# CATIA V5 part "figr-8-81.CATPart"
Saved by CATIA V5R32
Part number: Part1
Bounding box of the stored display mesh (mm): x -52.625 to 52.625, y -77.625 to 77.625, z 0 to 30
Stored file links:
  D:\PROJECTS\Project 2022\CATIA V5 6R 2022\Resources\Part Files\c08_catia_v5_6r2022_prt\figr-8-81.CATPart
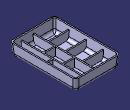
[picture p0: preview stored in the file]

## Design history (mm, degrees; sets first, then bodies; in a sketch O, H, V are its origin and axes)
Set1
  Plane1: type Offset, RefPlane xy-plane, Offset 30
  Plane2: type Offset, RefPlane face of Pad1, Offset -8, reversed
Body1 (main body)
  Sketch1 on xy-plane, origin (0, 0, 0), H (1, 0, 0), V (0, 1, 0)
    line L1 (-50, 75) -> (50, 75)
    line L2 (50, 75) -> (50, -75)
    line L3 (50, -75) -> (-50, -75)
    line L4 (-50, -75) -> (-50, 75)
    axis line L5 (50, -75) -> (-50, 75)
    length L3 = 100
    length L2 = 150
    horizontal: L1 H, L3 H
    vertical: L2 V, L4 V
    midpoint: O L5
  Pad1: profile Sketch1, direction (0, 0, 1), length 0, opposite side up to Plane1
  Draft1: Angle -5, Neutral face of Pad1, PullDir face of Pad1, SupportToDraft (face of Pad1; face of Pad1; face of Pad1; face of Pad1)
  Fillet1: radius 7, on edge [face of Pad1 | face of Pad1] (x4)
  Fillet2: radius 10, on edge [face of Pad1 | face of Pad1] (x4)
  Shell1: ExtOffset 0, Face face of Pad1, IntOffset 3
  Sketch2 on Plane2, origin (0, 0, 22), H (1, 0, 0), V (0, -1, 0)
    line L1 (28.1747, 54.0191) -> (28.1747, -59.2866)
    line L2 (0, 54.0191) -> (0, -59.2866)
    point P3 (0, 54.0191)
    line L3 (-9.5939, 0) -> (-33.0562, 0)
    point P5 (-9.5939, 0)
    line L4 (-9.5939, -40.4023) -> (-33.0562, -40.4023)
    point P7 (-9.5939, -40.4023)
    point P8 (-33.0562, -40.4023)
    point P9 (-33.0562, 40.4023)
    point P10 (-9.5939, 40.4023)
    line L5 (-9.5939, 40.4023) -> (-33.0562, 40.4023)
    line L6 (28.1747, 22.6983) -> (0, 22.6983)
    point P11 (28.1747, 22.6983)
    point P12 (0, 22.6983)
    point P13 (0, -22.6983)
    point P14 (28.1747, -22.6983)
    line L7 (28.1747, -22.6983) -> (0, -22.6983)
    line L8 (28.1747, 0) -> (41.8849, 0)
    point P15 (28.1747, 0)
    vertical: L1 V, L2 V
    coincidence: P3 V, P5 H, P11 L1, P12 L2, P15 L1, P15 H
    horizontal: L3 H, L4 H, L6 H, L8 H
    symmetry: P8 P9 L3, P7 P10 L3, L4 L5 L3, P12 P13 H, P11 P14 H, L6 L7 H
  Stiffener1: ExtendedProfile Sketch2, ThicknessTop 1, ThicknessValue 3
